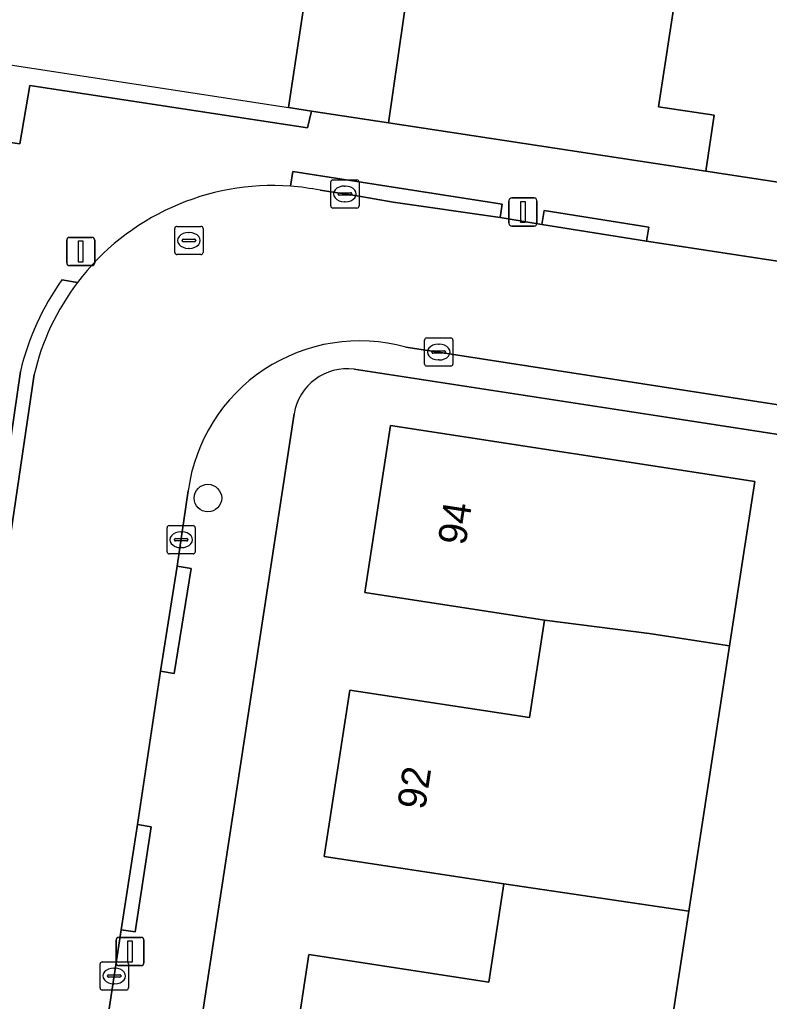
# Model space of a CAD drawing. Extents: x 161483 to 162250, y 379484 to 380833.
# Drawn here: x 161945.57 to 161972.16, y 380711.06 to 380745.87 of the extents above; entities that cross this region are included whole.
import ezdxf

# ---------------------------------------------------------------- set-up
doc = ezdxf.new("R2010")
doc.units = 0
for name, color, linetype in [('IMGEO_Boom', 7, 'Continuous'), ('IMGEO_Erf', 7, 'Continuous'), ('IMGEO_Kolk', 7, 'Continuous'), ('IMGEO_Lichtmast', 7, 'Continuous'), ('IMGEO_Muur', 7, 'Continuous'), ('IMGEO_Pand', 7, 'Continuous'), ('IMGEO_Pand_nummerreeks', 7, 'Continuous'), ('IMGEO_Rijbaan_lokaal_open', 7, 'Continuous'), ('IMGEO_Rioolput', 7, 'Continuous'), ('IMGEO_Voetpad_open', 7, 'Continuous')]:
    doc.layers.add(name, color=color, linetype=linetype)

msp = doc.modelspace()

# ---------------------------------------------------------------- linework, layer by layer
at = {"layer": 'IMGEO_Boom'}
msp.add_circle((161952.251, 380728.904), 0.489, dxfattribs=at)
at = {"layer": 'IMGEO_Erf'}
for points in [[(161968.855, 380746.865), (161968.233, 380742.782), (161970.21, 380742.48), (161969.907, 380740.493), (161983.164, 380738.471), (161984.094, 380744.572), (161988.554, 380743.892), (161988.91, 380743.838), (161988.952, 380744.114), (161992.856, 380743.519), (161991.884, 380737.142), (162006.07, 380734.98), (162007.048, 380741.396), (162010.684, 380740.841), (162014.59, 380740.245), (162013.612, 380733.829), (162020.903, 380732.668), (162020.884, 380732.317), (162033.612, 380730.332), (162034.458, 380735.482), (162036.685, 380750)], [(161943.256, 380741.795), (161945.58, 380741.467), (161945.932, 380743.53), (161955.778, 380742.035), (161955.926, 380742.626), (161955.105, 380742.751), (161956.12, 380749.405)], [(162020.445, 380644.581), (162030.496, 380709.789), (162031.542, 380716.615), (162024.026, 380717.715), (162024.102, 380718.247), (162000, 380721.938), (161993.02, 380723.007), (161992.867, 380723.03), (161992.821, 380722.728), (161984.494, 380724.06), (161985.301, 380729.182), (161981.521, 380729.764), (161968.659, 380731.745), (161957.44, 380733.472)], [(161955.311, 380731.889), (161949.611, 380694.604), (161942.94, 380651.025), (161940.472, 380634.904), (161938.44, 380621.627), (161934.347, 380594.923)], [(161954.932, 380706.791), (161955.83, 380712.72), (161962.213, 380711.737), (161962.749, 380715.223), (161956.38, 380716.19), (161957.287, 380722.098), (161963.656, 380721.118), (161964.188, 380724.575), (161957.818, 380725.554), (161958.73, 380731.48), (161971.65, 380729.49), (161971.239, 380726.824), (161970.753, 380723.664), (161969.79, 380717.414), (161969.304, 380714.255), (161968.345, 380708.025)]]:
    msp.add_lwpolyline(points, dxfattribs=at)
msp.add_arc((161957.183, 380731.594), 1.895, 82.2054, 171.0593, dxfattribs=at)
at = {"layer": 'IMGEO_Kolk'}
for p, q in [((161956.61, 380739.264), (161956.61, 380740.116)), ((161956.685, 380740.19), (161957.537, 380740.19)), ((161957.611, 380740.116), (161957.611, 380739.264)), ((161956.869, 380739.684), (161956.869, 380739.696)), ((161956.912, 380739.733), (161957.31, 380739.733)), ((161957.098, 380739.97), (161957.123, 380739.97)), ((161957.353, 380739.696), (161957.353, 380739.684)), ((161957.307, 380739.647), (161956.909, 380739.647)), ((161957.121, 380739.41), (161957.096, 380739.41)), ((161957.537, 380739.19), (161956.685, 380739.19)), ((161959.937, 380733.657), (161959.937, 380734.509)), ((161960.012, 380734.583), (161960.864, 380734.583)), ((161960.938, 380734.509), (161960.938, 380733.657)), ((161960.239, 380734.126), (161960.637, 380734.126)), ((161960.425, 380734.363), (161960.45, 380734.363)), ((161960.196, 380734.077), (161960.196, 380734.089)), ((161960.634, 380734.04), (161960.236, 380734.04)), ((161960.448, 380733.803), (161960.423, 380733.803)), ((161960.68, 380734.089), (161960.68, 380734.077)), ((161960.864, 380733.583), (161960.012, 380733.583)), ((161950.802, 380727.001), (161950.802, 380727.853)), ((161950.877, 380727.927), (161951.729, 380727.927)), ((161951.803, 380727.853), (161951.803, 380727.001)), ((161951.29, 380727.707), (161951.315, 380727.707)), ((161951.061, 380727.421), (161951.061, 380727.433)), ((161951.499, 380727.384), (161951.101, 380727.384)), ((161951.104, 380727.47), (161951.502, 380727.47)), ((161951.313, 380727.147), (161951.288, 380727.147)), ((161951.545, 380727.433), (161951.545, 380727.421)), ((161951.729, 380726.927), (161950.877, 380726.927)), ((161948.429, 380711.531), (161948.429, 380712.383)), ((161948.504, 380712.457), (161949.356, 380712.457)), ((161948.917, 380712.237), (161948.942, 380712.237)), ((161949.43, 380712.383), (161949.43, 380711.531)), ((161948.688, 380711.951), (161948.688, 380711.963)), ((161949.126, 380711.914), (161948.728, 380711.914)), ((161948.731, 380712), (161949.129, 380712)), ((161949.172, 380711.963), (161949.172, 380711.951)), ((161948.94, 380711.677), (161948.915, 380711.677)), ((161949.356, 380711.457), (161948.504, 380711.457))]:
    msp.add_line(p, q, dxfattribs=at)
for points in [[(161956.61, 380739.264), (161956.61, 380740.116)], [(161956.685, 380740.19), (161957.537, 380740.19)], [(161957.611, 380740.116), (161957.611, 380739.264)], [(161957.537, 380739.19), (161956.685, 380739.19)], [(161959.937, 380733.657), (161959.937, 380734.509)], [(161960.012, 380734.583), (161960.864, 380734.583)], [(161960.938, 380734.509), (161960.938, 380733.657)], [(161960.864, 380733.583), (161960.012, 380733.583)], [(161950.802, 380727.001), (161950.802, 380727.853)], [(161950.877, 380727.927), (161951.729, 380727.927)], [(161951.803, 380727.853), (161951.803, 380727.001)], [(161951.729, 380726.927), (161950.877, 380726.927)], [(161948.429, 380711.531), (161948.429, 380712.383)], [(161948.504, 380712.457), (161949.356, 380712.457)], [(161949.43, 380712.383), (161949.43, 380711.531)], [(161949.356, 380711.457), (161948.504, 380711.457)]]:
    msp.add_lwpolyline(points, dxfattribs=at)
for centre, radius, start, end in [((161956.687, 380740.114), 0.0765, 91.552, 178.448), ((161956.687, 380740.114), 0.0765, 91.552, 178.448), ((161957.535, 380740.114), 0.0765, 1.552, 88.448), ((161957.535, 380740.114), 0.0765, 1.552, 88.448), ((161956.909, 380739.693), 0.0403, 85.8775, 175.7526), ((161956.906, 380739.683), 0.0366, 178.938, 274.7102), ((161957.31, 380739.69), 0.043, 264.8664, 352.4533), ((161957.314, 380739.695), 0.0386, 1.7309, 96.639), ((161956.687, 380739.266), 0.0765, 181.552, 268.448), ((161956.687, 380739.266), 0.0765, 181.552, 268.448), ((161957.535, 380739.266), 0.0765, 271.552, 358.448), ((161957.535, 380739.266), 0.0765, 271.552, 358.448), ((161960.014, 380734.507), 0.0765, 91.552, 178.448), ((161960.014, 380734.507), 0.0765, 91.552, 178.448), ((161960.862, 380734.507), 0.0765, 1.552, 88.448), ((161960.862, 380734.507), 0.0765, 1.552, 88.448), ((161960.236, 380734.086), 0.0403, 85.8775, 175.7526), ((161960.641, 380734.088), 0.0386, 1.7309, 96.639), ((161960.233, 380734.076), 0.0366, 178.938, 274.7102), ((161960.637, 380734.083), 0.043, 264.8664, 352.4533), ((161960.014, 380733.659), 0.0765, 181.552, 268.448), ((161960.014, 380733.659), 0.0765, 181.552, 268.448), ((161960.862, 380733.659), 0.0765, 271.552, 358.448), ((161960.862, 380733.659), 0.0765, 271.552, 358.448), ((161950.879, 380727.851), 0.0765, 91.552, 178.448), ((161950.879, 380727.851), 0.0765, 91.552, 178.448), ((161951.727, 380727.851), 0.0765, 1.552, 88.448), ((161951.727, 380727.851), 0.0765, 1.552, 88.448), ((161951.101, 380727.43), 0.0403, 85.8775, 175.7526), ((161951.098, 380727.42), 0.0366, 178.938, 274.7102), ((161951.502, 380727.427), 0.043, 264.8664, 352.4533), ((161951.506, 380727.432), 0.0386, 1.7309, 96.639), ((161950.879, 380727.003), 0.0765, 181.552, 268.448), ((161950.879, 380727.003), 0.0765, 181.552, 268.448), ((161951.727, 380727.003), 0.0765, 271.552, 358.448), ((161951.727, 380727.003), 0.0765, 271.552, 358.448), ((161948.506, 380712.381), 0.0765, 91.552, 178.448), ((161948.506, 380712.381), 0.0765, 91.552, 178.448), ((161949.354, 380712.381), 0.0765, 1.552, 88.448), ((161949.354, 380712.381), 0.0765, 1.552, 88.448), ((161948.728, 380711.96), 0.0403, 85.8775, 175.7526), ((161948.725, 380711.95), 0.0366, 178.938, 274.7102), ((161949.129, 380711.957), 0.043, 264.8664, 352.4533), ((161949.133, 380711.962), 0.0386, 1.7309, 96.639), ((161948.506, 380711.533), 0.0765, 181.552, 268.448), ((161948.506, 380711.533), 0.0765, 181.552, 268.448), ((161949.354, 380711.533), 0.0765, 271.552, 358.448), ((161949.354, 380711.533), 0.0765, 271.552, 358.448)]:
    msp.add_arc(centre, radius, start, end, dxfattribs=at)
for centre, major_axis, ratio, start_param, end_param in [((161957.097, 380739.69), (-0.387, 0.002), 0.722429, 4.712389, 7.853982), ((161957.122, 380739.69), (-0.39, 0.002), 0.717154, 1.570796, 4.712389), ((161960.424, 380734.083), (-0.387, 0.002), 0.722429, 4.712389, 7.853982), ((161960.449, 380734.083), (-0.39, 0.002), 0.717154, 1.570796, 4.712389), ((161951.289, 380727.427), (-0.387, 0.002), 0.722429, 4.712389, 7.853982), ((161951.314, 380727.427), (-0.39, 0.002), 0.717154, 1.570796, 4.712389), ((161948.916, 380711.957), (-0.387, 0.002), 0.722429, 4.712389, 7.853982), ((161948.941, 380711.957), (-0.39, 0.002), 0.717154, 1.570796, 4.712389)]:
    msp.add_ellipse(centre, major_axis=major_axis, ratio=ratio, start_param=start_param, end_param=end_param, dxfattribs=at)
at = {"layer": 'IMGEO_Lichtmast'}
for p, q in [((161962.929, 380738.651), (161962.929, 380739.451)), ((161962.929, 380739.451), (161962.929, 380738.651)), ((161963.029, 380739.551), (161963.819, 380739.551)), ((161963.819, 380739.551), (161963.029, 380739.551)), ((161963.919, 380739.451), (161963.919, 380738.651)), ((161963.919, 380738.651), (161963.919, 380739.451)), ((161963.819, 380738.551), (161963.029, 380738.551)), ((161963.029, 380738.551), (161963.819, 380738.551)), ((161947.246, 380737.249), (161947.246, 380738.049)), ((161947.246, 380738.049), (161947.246, 380737.249)), ((161947.346, 380738.149), (161948.136, 380738.149)), ((161948.136, 380738.149), (161947.346, 380738.149)), ((161948.236, 380738.049), (161948.236, 380737.249)), ((161948.236, 380737.249), (161948.236, 380738.049)), ((161948.136, 380737.149), (161947.346, 380737.149)), ((161947.346, 380737.149), (161948.136, 380737.149)), ((161948.995, 380712.424), (161948.995, 380713.224)), ((161948.995, 380713.224), (161948.995, 380712.424)), ((161949.095, 380713.324), (161949.885, 380713.324)), ((161949.885, 380713.324), (161949.095, 380713.324)), ((161949.985, 380713.224), (161949.985, 380712.424)), ((161949.985, 380712.424), (161949.985, 380713.224)), ((161949.885, 380712.324), (161949.095, 380712.324)), ((161949.095, 380712.324), (161949.885, 380712.324))]:
    msp.add_line(p, q, dxfattribs=at)
for points in [[(161963.349, 380739.426), (161963.499, 380739.426), (161963.499, 380738.676), (161963.349, 380738.676), (161963.349, 380739.426)], [(161947.666, 380738.024), (161947.816, 380738.024), (161947.816, 380737.274), (161947.666, 380737.274), (161947.666, 380738.024)], [(161949.415, 380713.199), (161949.565, 380713.199), (161949.565, 380712.449), (161949.415, 380712.449), (161949.415, 380713.199)]]:
    msp.add_lwpolyline(points, dxfattribs=at)
for centre, start, end in [((161963.029, 380739.451), 90, 180), ((161963.029, 380739.451), 90, 180), ((161963.819, 380739.451), 0, 90), ((161963.819, 380739.451), 360, 90), ((161963.029, 380738.651), 180, 270), ((161963.029, 380738.651), 180, 270), ((161963.819, 380738.651), 270, 0), ((161963.819, 380738.651), 270, 0), ((161947.346, 380738.049), 90, 180), ((161947.346, 380738.049), 90, 180), ((161948.136, 380738.049), 0, 90), ((161948.136, 380738.049), 360, 90), ((161947.346, 380737.249), 180, 270), ((161947.346, 380737.249), 180, 270), ((161948.136, 380737.249), 270, 0), ((161948.136, 380737.249), 270, 0), ((161949.095, 380713.224), 90, 180), ((161949.095, 380713.224), 90, 180), ((161949.885, 380713.224), 0, 90), ((161949.885, 380713.224), 360, 90), ((161949.095, 380712.424), 180, 270), ((161949.095, 380712.424), 180, 270), ((161949.885, 380712.424), 270, 0), ((161949.885, 380712.424), 270, 0)]:
    msp.add_arc(centre, 0.1, start, end, dxfattribs=at)
at = {"layer": 'IMGEO_Muur'}
for points in [[(161942.53, 380744.682), (161955.105, 380742.751)], [(161969.907, 380740.493), (161983.164, 380738.471)], [(161968.659, 380731.745), (161981.521, 380729.764)]]:
    msp.add_lwpolyline(points, dxfattribs=at)
at = {"layer": 'IMGEO_Pand'}
for points in [[(161959.529, 380748.287), (161959.613, 380748.872), (161956.12, 380749.405), (161955.105, 380742.751), (161955.926, 380742.626), (161958.651, 380742.21)], [(161959.728, 380748.257), (161959.529, 380748.287), (161958.651, 380742.21), (161969.907, 380740.493), (161970.21, 380742.48), (161968.233, 380742.782), (161968.855, 380746.865), (161960.246, 380748.178)], [(161964.188, 380724.575), (161967.899, 380724.104), (161970.753, 380723.664), (161971.239, 380726.824), (161971.65, 380729.49), (161958.73, 380731.48), (161957.818, 380725.554)], [(161964.188, 380724.575), (161963.656, 380721.118), (161957.287, 380722.098), (161956.38, 380716.19), (161962.749, 380715.223), (161969.304, 380714.255), (161969.79, 380717.414), (161970.753, 380723.664), (161967.899, 380724.104)], [(161961.302, 380705.811), (161965.007, 380705.315), (161965.492, 380708.464), (161968.345, 380708.025), (161969.304, 380714.255), (161962.749, 380715.223), (161962.213, 380711.737), (161955.83, 380712.72), (161954.932, 380706.791)]]:
    msp.add_lwpolyline(points, close=True, dxfattribs=at)
at = {"layer": 'IMGEO_Rijbaan_lokaal_open'}
for points in [[(162031.18, 380728.288), (162024.021, 380729.387), (162013.189, 380731.055), (162009.631, 380731.602), (162003.754, 380732.507), (162000, 380733.095), (161991.346, 380734.451), (161987.613, 380734.977), (161984.458, 380735.473), (161967.812, 380738.019), (161964.1, 380738.605), (161962.617, 380738.853), (161958.821, 380739.397), (161957.472, 380739.634), (161956.237, 380739.82)], [(161959.267, 380734.253), (161960.434, 380734.084), (161981.182, 380730.869), (161981.502, 380730.873), (161991.837, 380729.246)], [(161946.089, 380733.283), (161945.135, 380726.778), (161945.082, 380726.553), (161943.407, 380715.95), (161943.296, 380715.222), (161940.897, 380699.445), (161940.819, 380699.188), (161940.771, 380698.875), (161933.359, 380650.594), (161932.427, 380644.579), (161931.61, 380638.889), (161931.551, 380638.667)], [(161947.699, 380704.067), (161948.294, 380707.766), (161949.178, 380713.594), (161949.75, 380717.326), (161950.566, 380722.765), (161951.16, 380726.486), (161951.552, 380729.165)]]:
    msp.add_lwpolyline(points, dxfattribs=at)
for centre, radius, start, end in [((161954.549, 380731.293), 8.693, 85.8378, 142.8237), ((161954.567, 380731.454), 8.531, 78.7112, 85.8795), ((161954.552, 380731.297), 8.693, 142.8511, 166.7906), ((161957.623, 380728.353), 6.125, 74.431, 172.3783)]:
    msp.add_arc(centre, radius, start, end, dxfattribs=at)
at = {"layer": 'IMGEO_Rioolput'}
for p, q in [((161951.077, 380737.614), (161951.077, 380738.466)), ((161951.152, 380738.54), (161952.004, 380738.54)), ((161951.565, 380738.32), (161951.59, 380738.32)), ((161952.078, 380738.466), (161952.078, 380737.614)), ((161951.336, 380738.034), (161951.336, 380738.046)), ((161951.774, 380737.997), (161951.376, 380737.997)), ((161951.379, 380738.083), (161951.777, 380738.083)), ((161951.82, 380738.046), (161951.82, 380738.034)), ((161951.588, 380737.76), (161951.563, 380737.76)), ((161952.004, 380737.54), (161951.152, 380737.54))]:
    msp.add_line(p, q, dxfattribs=at)
for points in [[(161951.077, 380737.614), (161951.077, 380738.466)], [(161951.152, 380738.54), (161952.004, 380738.54)], [(161952.078, 380738.466), (161952.078, 380737.614)], [(161952.004, 380737.54), (161951.152, 380737.54)]]:
    msp.add_lwpolyline(points, dxfattribs=at)
for centre, radius, start, end in [((161951.154, 380738.464), 0.0765, 91.552, 178.448), ((161951.154, 380738.464), 0.0765, 91.552, 178.448), ((161952.002, 380738.464), 0.0765, 1.552, 88.448), ((161952.002, 380738.464), 0.0765, 1.552, 88.448), ((161951.376, 380738.043), 0.0403, 85.8775, 175.7526), ((161951.373, 380738.033), 0.0366, 178.938, 274.7102), ((161951.777, 380738.04), 0.043, 264.8664, 352.4533), ((161951.781, 380738.045), 0.0386, 1.7309, 96.639), ((161951.154, 380737.616), 0.0765, 181.552, 268.448), ((161951.154, 380737.616), 0.0765, 181.552, 268.448), ((161952.002, 380737.616), 0.0765, 271.552, 358.448), ((161952.002, 380737.616), 0.0765, 271.552, 358.448)]:
    msp.add_arc(centre, radius, start, end, dxfattribs=at)
for centre, major_axis, ratio, start_param, end_param in [((161951.564, 380738.04), (-0.387, 0.002), 0.722429, 4.712389, 7.853982), ((161951.589, 380738.04), (-0.39, 0.002), 0.717154, 1.570796, 4.712389)]:
    msp.add_ellipse(centre, major_axis=major_axis, ratio=ratio, start_param=start_param, end_param=end_param, dxfattribs=at)
at = {"layer": 'IMGEO_Voetpad_open'}
for points in [[(162033.278, 380728.387), (162033.612, 380730.332), (162020.884, 380732.317), (162020.903, 380732.668), (162013.612, 380733.829), (162009.83, 380734.406), (162006.07, 380734.98), (161991.884, 380737.142), (161987.708, 380737.778), (161983.164, 380738.471), (161969.907, 380740.493), (161958.651, 380742.21), (161955.926, 380742.626), (161955.778, 380742.035), (161945.932, 380743.53), (161945.58, 380741.467), (161943.256, 380741.795), (161938.583, 380711.252), (161937.319, 380702.795), (161927.438, 380638.646)], [(161956.237, 380739.82), (161957.472, 380739.634), (161958.821, 380739.397), (161962.617, 380738.853), (161962.69, 380739.328), (161955.26, 380740.486), (161955.18, 380739.963)], [(161955.18, 380739.963), (161955.26, 380740.486), (161962.69, 380739.328), (161962.617, 380738.853), (161964.1, 380738.605), (161964.177, 380739.098), (161967.889, 380738.512), (161967.812, 380738.019), (161984.458, 380735.473), (161987.613, 380734.977), (161987.682, 380735.472), (161991.415, 380734.946), (161991.346, 380734.451), (162000, 380733.095), (162003.754, 380732.507), (162009.631, 380731.602), (162009.698, 380732.042), (162013.257, 380731.499), (162013.189, 380731.055), (162024.021, 380729.387), (162031.18, 380728.288)], [(161947.623, 380736.546), (161947.073, 380736.642)], [(161947.073, 380736.642), (161947.623, 380736.546)], [(161991.837, 380729.246), (161991.76, 380728.753), (161981.425, 380730.38), (161981.502, 380730.873), (161981.182, 380730.869), (161960.434, 380734.084), (161959.267, 380734.253)], [(161945.602, 380733.397), (161944.608, 380726.634), (161945.082, 380726.553), (161945.135, 380726.778), (161946.089, 380733.283)], [(161945.082, 380726.553), (161944.608, 380726.634), (161945.602, 380733.397)], [(161957.44, 380733.472), (161968.659, 380731.745), (161981.521, 380729.764), (161985.301, 380729.182), (161984.494, 380724.06), (161992.821, 380722.728), (161992.867, 380723.03), (161993.02, 380723.007), (161993.624, 380727.014)], [(161927.166, 380621.505), (161926.845, 380619.322), (161927.469, 380619.219), (161932.392, 380618.524), (161932.982, 380622.467), (161938.44, 380621.627), (161940.472, 380634.904), (161942.94, 380651.025), (161949.611, 380694.604), (161955.311, 380731.889)], [(161951.552, 380729.165), (161951.16, 380726.486), (161951.653, 380726.408), (161951.059, 380722.687), (161950.566, 380722.765), (161949.75, 380717.326), (161950.244, 380717.251), (161949.672, 380713.519), (161949.178, 380713.594), (161948.294, 380707.766), (161948.787, 380707.687), (161948.192, 380703.988), (161947.699, 380704.067), (161946.856, 380698.453), (161947.35, 380698.377), (161946.766, 380694.629), (161946.272, 380694.705), (161945.442, 380689.115), (161945.935, 380689.037), (161945.345, 380685.325)]]:
    msp.add_lwpolyline(points, dxfattribs=at)
for points in [[(161967.812, 380738.019), (161967.889, 380738.512), (161964.177, 380739.098), (161964.1, 380738.605)], [(161951.16, 380726.486), (161950.566, 380722.765), (161951.059, 380722.687), (161951.653, 380726.408)], [(161949.178, 380713.594), (161949.672, 380713.519), (161950.244, 380717.251), (161949.75, 380717.326)]]:
    msp.add_lwpolyline(points, close=True, dxfattribs=at)
for centre, radius, start, end in [((161954.549, 380731.293), 8.693, 85.8378, 142.8237), ((161954.567, 380731.454), 8.531, 78.7112, 85.8795), ((161954.57, 380731.288), 9.212, 144.4649, 166.7643), ((161954.57, 380731.288), 9.212, 144.4649, 166.7643), ((161954.552, 380731.297), 8.693, 142.8511, 166.7906), ((161957.623, 380728.353), 6.125, 74.431, 172.3783), ((161957.183, 380731.594), 1.895, 82.2054, 171.0593)]:
    msp.add_arc(centre, radius, start, end, dxfattribs=at)

# ---------------------------------------------------------------- texts
at = {"layer": 'IMGEO_Pand_nummerreeks'}
for s, rotation, p in [('94', 81.2511, (161961.389, 380727.201)), ('92', 81.2721, (161959.95, 380717.826))]:
    msp.add_text(s, height=1, rotation=rotation, dxfattribs=at).set_placement(p)

doc.saveas('drawing.dxf')
